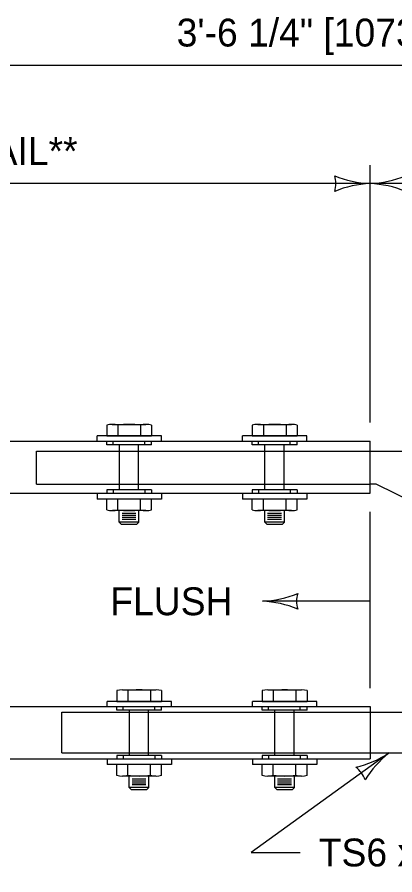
# Model space of a CAD drawing. Extents: x 49991.4 to 50021, y 49987.6 to 50011.4.
# Drawn here: x 50001.527 to 50002.34, y 49993.076 to 49994.923 of the extents above; entities that cross this region are included whole.
import ezdxf

# ---------------------------------------------------------------- set-up
doc = ezdxf.new("R2010")
doc.units = 0
for name, color, linetype in [('Level 1', 7, 'Continuous'), ('Level 2', 7, 'Continuous'), ('Level 3', 7, 'Continuous'), ('Level 4', 7, 'Continuous')]:
    doc.layers.add(name, color=color, linetype=linetype)

msp = doc.modelspace()

# ---------------------------------------------------------------- linework, layer by layer
at = {"layer": 'Level 1'}
for p, q in [((50001.7195, 49994.0446), (50001.7195, 49994.0215)), ((50001.7316, 49994.0461), (50001.8039, 49994.0461)), ((50001.7434, 49994.0446), (50001.7434, 49994.0216)), ((50001.7922, 49994.0446), (50001.7922, 49994.0216)), ((50001.8161, 49994.0446), (50001.8161, 49994.0215)), ((50002.0327, 49994.0446), (50002.0327, 49994.0215)), ((50002.0448, 49994.0461), (50002.1171, 49994.0461)), ((50002.0566, 49994.0446), (50002.0566, 49994.0216)), ((50002.1054, 49994.0446), (50002.1054, 49994.0216)), ((50002.1293, 49994.0446), (50002.1293, 49994.0215)), ((50001.4285, 49994.0102), (50002.2862, 49994.0102)), ((50001.8371, 49994.0215), (50001.6988, 49994.0215)), ((50001.6988, 49994.0102), (50001.6988, 49994.0215)), ((50001.7195, 49994.0215), (50001.8161, 49994.0215)), ((50001.8371, 49994.0102), (50001.8371, 49994.0215)), ((50002.1503, 49994.0215), (50002.012, 49994.0215)), ((50002.012, 49994.0102), (50002.012, 49994.0215)), ((50002.0327, 49994.0215), (50002.1293, 49994.0215)), ((50002.1503, 49994.0102), (50002.1503, 49994.0215)), ((50002.2862, 49993.8979), (50002.2862, 49994.0102)), ((50002.2862, 49993.9889), (50002.717, 49993.9889)), ((50002.2864, 49993.9179), (50002.2997, 49993.9179)), ((50002.717, 49993.7093), (50002.2992, 49993.9177)), ((50001.3976, 49993.8979), (50002.2862, 49993.8979)), ((50001.6988, 49993.8979), (50001.6988, 49993.8853)), ((50001.8371, 49993.8979), (50001.8371, 49993.8853)), ((50002.012, 49993.8979), (50002.012, 49993.8853)), ((50002.1503, 49993.8979), (50002.1503, 49993.8853)), ((50001.8371, 49993.8853), (50001.6988, 49993.8853)), ((50001.8161, 49993.8853), (50001.7195, 49993.8853)), ((50001.7195, 49993.8622), (50001.7195, 49993.8853)), ((50001.7434, 49993.8622), (50001.7434, 49993.8852)), ((50001.7922, 49993.8622), (50001.7922, 49993.8852)), ((50001.8161, 49993.8622), (50001.8161, 49993.8853)), ((50002.1503, 49993.8853), (50002.012, 49993.8853)), ((50002.1293, 49993.8853), (50002.0327, 49993.8853)), ((50002.0327, 49993.8622), (50002.0327, 49993.8853)), ((50002.0566, 49993.8622), (50002.0566, 49993.8852)), ((50002.1054, 49993.8622), (50002.1054, 49993.8852)), ((50002.1293, 49993.8622), (50002.1293, 49993.8853)), ((50001.804, 49993.8607), (50001.7317, 49993.8607)), ((50001.7466, 49993.8358), (50001.7466, 49993.8608)), ((50001.7888, 49993.8358), (50001.7888, 49993.8608)), ((50002.1172, 49993.8607), (50002.0449, 49993.8607)), ((50002.0598, 49993.8358), (50002.0598, 49993.8608)), ((50002.102, 49993.8358), (50002.102, 49993.8608)), ((50001.7527, 49993.8549), (50001.7824, 49993.8549)), ((50001.7527, 49993.8507), (50001.7824, 49993.8507)), ((50001.7527, 49993.8464), (50001.7824, 49993.8464)), ((50001.7527, 49993.8422), (50001.7824, 49993.8422)), ((50002.0659, 49993.8549), (50002.0956, 49993.8549)), ((50002.0659, 49993.8507), (50002.0956, 49993.8507)), ((50002.0659, 49993.8464), (50002.0956, 49993.8464)), ((50002.0659, 49993.8422), (50002.0956, 49993.8422)), ((50001.7888, 49993.8358), (50001.7466, 49993.8358)), ((50001.7466, 49993.8358), (50001.7508, 49993.8316)), ((50001.7508, 49993.8316), (50001.7846, 49993.8316)), ((50001.7888, 49993.8358), (50001.7846, 49993.8316)), ((50002.102, 49993.8358), (50002.0598, 49993.8358)), ((50002.0598, 49993.8358), (50002.064, 49993.8316)), ((50002.064, 49993.8316), (50002.0978, 49993.8316)), ((50002.102, 49993.8358), (50002.0978, 49993.8316)), ((50001.7411, 49993.4731), (50001.7411, 49993.45)), ((50001.7532, 49993.4746), (50001.8255, 49993.4746)), ((50001.765, 49993.4731), (50001.765, 49993.4501)), ((50001.8138, 49993.4731), (50001.8138, 49993.4501)), ((50001.8377, 49993.4731), (50001.8377, 49993.45)), ((50002.0541, 49993.4731), (50002.0541, 49993.45)), ((50002.0662, 49993.4746), (50002.1385, 49993.4746)), ((50002.078, 49993.4731), (50002.078, 49993.4501)), ((50002.1268, 49993.4731), (50002.1268, 49993.4501)), ((50002.1507, 49993.4731), (50002.1507, 49993.45)), ((50000.5502, 49993.4387), (50002.2862, 49993.4387)), ((50001.8587, 49993.45), (50001.7204, 49993.45)), ((50001.7204, 49993.4387), (50001.7204, 49993.45)), ((50001.7411, 49993.45), (50001.8377, 49993.45)), ((50001.8587, 49993.4387), (50001.8587, 49993.45)), ((50002.1717, 49993.45), (50002.0334, 49993.45)), ((50002.0334, 49993.4387), (50002.0334, 49993.45)), ((50002.0541, 49993.45), (50002.1507, 49993.45)), ((50002.1717, 49993.4387), (50002.1717, 49993.45)), ((50002.2862, 49993.4387), (50002.2862, 49993.3264)), ((50002.2862, 49993.4266), (50002.3682, 49993.4266)), ((50000.5502, 49993.3264), (50002.2862, 49993.3264)), ((50001.7204, 49993.3264), (50001.7204, 49993.3138)), ((50001.8587, 49993.3264), (50001.8587, 49993.3138)), ((50002.0334, 49993.3264), (50002.0334, 49993.3138)), ((50002.1717, 49993.3264), (50002.1717, 49993.3138)), ((50002.2862, 49993.3388), (50002.3682, 49993.3388)), ((50001.8587, 49993.3138), (50001.7204, 49993.3138)), ((50001.8377, 49993.3138), (50001.7411, 49993.3138)), ((50001.7411, 49993.2907), (50001.7411, 49993.3138)), ((50001.765, 49993.2907), (50001.765, 49993.3137)), ((50001.8138, 49993.2907), (50001.8138, 49993.3137)), ((50001.8377, 49993.2907), (50001.8377, 49993.3138)), ((50002.1717, 49993.3138), (50002.0334, 49993.3138)), ((50002.1507, 49993.3138), (50002.0541, 49993.3138)), ((50002.0541, 49993.2907), (50002.0541, 49993.3138)), ((50002.078, 49993.2907), (50002.078, 49993.3137)), ((50002.1268, 49993.2907), (50002.1268, 49993.3137)), ((50002.1507, 49993.2907), (50002.1507, 49993.3138)), ((50001.8256, 49993.2892), (50001.7533, 49993.2892)), ((50001.7682, 49993.2643), (50001.7682, 49993.2893)), ((50001.8104, 49993.2643), (50001.8104, 49993.2893)), ((50002.1386, 49993.2892), (50002.0663, 49993.2892)), ((50002.0812, 49993.2643), (50002.0812, 49993.2893)), ((50002.1234, 49993.2643), (50002.1234, 49993.2893)), ((50001.7743, 49993.2834), (50001.804, 49993.2834)), ((50001.7743, 49993.2792), (50001.804, 49993.2792)), ((50001.7743, 49993.2749), (50001.804, 49993.2749)), ((50001.7743, 49993.2707), (50001.804, 49993.2707)), ((50002.0873, 49993.2834), (50002.117, 49993.2834)), ((50002.0873, 49993.2792), (50002.117, 49993.2792)), ((50002.0873, 49993.2749), (50002.117, 49993.2749)), ((50002.0873, 49993.2707), (50002.117, 49993.2707)), ((50001.8104, 49993.2643), (50001.7682, 49993.2643)), ((50001.7682, 49993.2643), (50001.7724, 49993.2601)), ((50001.7724, 49993.2601), (50001.8062, 49993.2601)), ((50001.8104, 49993.2643), (50001.8062, 49993.2601)), ((50002.1234, 49993.2643), (50002.0812, 49993.2643)), ((50002.0812, 49993.2643), (50002.0854, 49993.2601)), ((50002.0854, 49993.2601), (50002.1192, 49993.2601)), ((50002.1234, 49993.2643), (50002.1192, 49993.2601))]:
    msp.add_line(p, q, dxfattribs=at)
for centre, major_axis, start_param, end_param in [((50001.7316, 49994.0344), (0.0242, 0), 1.056847, 2.094396), ((50001.7678, 49993.9994), (0.0966, 0), 1.315951, 1.825641), ((50001.804, 49994.0344), (0.0242, 0), 1.047198, 2.084746), ((50002.0448, 49994.0344), (0.0242, 0), 1.056847, 2.094396), ((50002.081, 49993.9994), (0.0966, 0), 1.315951, 1.825641), ((50002.1172, 49994.0344), (0.0242, 0), 1.047198, 2.084746), ((50001.7316, 49993.8724), (-0.0242, 0), 1.047198, 2.084746), ((50001.7678, 49993.9074), (-0.0966, 0), 1.315951, 1.825641), ((50001.804, 49993.8724), (-0.0242, 0), 1.056847, 2.094396), ((50002.0448, 49993.8724), (-0.0242, 0), 1.047198, 2.084746), ((50002.081, 49993.9074), (-0.0966, 0), 1.315951, 1.825641), ((50002.1172, 49993.8724), (-0.0242, 0), 1.056847, 2.094396), ((50001.7532, 49993.4629), (0.0242, 0), 1.056847, 2.094396), ((50001.7894, 49993.4279), (0.0966, 0), 1.315951, 1.825641), ((50001.8256, 49993.4629), (0.0242, 0), 1.047198, 2.084746), ((50002.0662, 49993.4629), (0.0242, 0), 1.056847, 2.094396), ((50002.1024, 49993.4279), (0.0966, 0), 1.315951, 1.825641), ((50002.1386, 49993.4629), (0.0242, 0), 1.047198, 2.084746), ((50001.7532, 49993.3009), (-0.0242, 0), 1.047198, 2.084746), ((50001.7894, 49993.3359), (-0.0966, 0), 1.315951, 1.825641), ((50001.8256, 49993.3009), (-0.0242, 0), 1.056847, 2.094396), ((50002.0662, 49993.3009), (-0.0242, 0), 1.047198, 2.084746), ((50002.1024, 49993.3359), (-0.0966, 0), 1.315951, 1.825641), ((50002.1386, 49993.3009), (-0.0242, 0), 1.056847, 2.094396)]:
    msp.add_ellipse(centre, major_axis=major_axis, ratio=0.483301, start_param=start_param, end_param=end_param, dxfattribs=at)
at = {"layer": 'Level 3'}
for p, q in [((50001.2319, 49994.8197), (50003.6098, 49994.8197)), ((50002.2862, 49994.0502), (50002.2862, 49994.6046)), ((50002.2862, 49994.5646), (50000.5502, 49994.5646)), ((50003.6098, 49994.5646), (50002.2862, 49994.5646)), ((50002.2862, 49993.4787), (50002.2862, 49993.8579)), ((50002.2862, 49993.6654), (50002.0545, 49993.6654)), ((50002.3273, 49993.3388), (50002.0304, 49993.1246)), ((50002.0304, 49993.1246), (50002.1358, 49993.1246))]:
    msp.add_line(p, q, dxfattribs=at)
for centre, radius, start, end in [((50002.2954, 49994.7867), 0.2223, 247.456, 267.6395), ((50002.158, 49994.5646), 0.0548, 342.1388, 17.8612), ((50002.2747, 49994.7973), 0.233, 272.8273, 292.0772), ((50002.2977, 49994.3319), 0.233, 92.8273, 112.0772), ((50002.277, 49994.3425), 0.2223, 67.456, 87.6395), ((50002.043, 49993.8982), 0.233, 272.8273, 292.0772), ((50002.1827, 49993.6654), 0.0548, 162.1388, 197.8612), ((50002.0454, 49993.4433), 0.2223, 67.456, 87.6395), ((50002.2048, 49993.5243), 0.2223, 283.2637, 303.4472), ((50002.4728, 49993.1568), 0.233, 128.635, 147.8848), ((50002.2234, 49993.2638), 0.0548, 17.9465, 53.6688)]:
    msp.add_arc(centre, radius, start, end, dxfattribs=at)
at = {"layer": 'Level 4'}
for p, q in [((50001.7195, 49994.0023), (50001.7195, 49994.0102)), ((50001.7331, 49994.0023), (50001.7331, 49994.0102)), ((50001.8015, 49994.0023), (50001.8015, 49994.0102)), ((50001.8161, 49994.0023), (50001.8161, 49994.0102)), ((50002.0327, 49994.0023), (50002.0327, 49994.0102)), ((50002.0463, 49994.0023), (50002.0463, 49994.0102)), ((50002.1147, 49994.0023), (50002.1147, 49994.0102)), ((50002.1293, 49994.0023), (50002.1293, 49994.0102)), ((50001.5686, 49993.9177), (50001.5686, 49993.9889)), ((50001.5686, 49993.9889), (50002.2862, 49993.9889)), ((50001.8161, 49994.0023), (50001.7195, 49994.0023)), ((50001.7468, 49993.9051), (50001.7468, 49994.0023)), ((50001.7882, 49993.9051), (50001.7882, 49994.0023)), ((50002.1293, 49994.0023), (50002.0327, 49994.0023)), ((50002.06, 49993.9051), (50002.06, 49994.0023)), ((50002.1014, 49993.9051), (50002.1014, 49994.0023)), ((50001.5686, 49993.9177), (50002.2862, 49993.9177)), ((50001.8161, 49993.9051), (50001.7195, 49993.9051)), ((50001.7195, 49993.9051), (50001.7195, 49993.8979)), ((50001.7331, 49993.9051), (50001.7331, 49993.8979)), ((50001.8015, 49993.9051), (50001.8015, 49993.8979)), ((50001.8161, 49993.9051), (50001.8161, 49993.8979)), ((50002.1293, 49993.9051), (50002.0327, 49993.9051)), ((50002.0327, 49993.9051), (50002.0327, 49993.8979)), ((50002.0463, 49993.9051), (50002.0463, 49993.8979)), ((50002.1147, 49993.9051), (50002.1147, 49993.8979)), ((50002.1293, 49993.9051), (50002.1293, 49993.8979)), ((50001.7411, 49993.4308), (50001.7411, 49993.4387)), ((50001.7547, 49993.4308), (50001.7547, 49993.4387)), ((50001.8231, 49993.4308), (50001.8231, 49993.4387)), ((50001.8377, 49993.4308), (50001.8377, 49993.4387)), ((50002.0541, 49993.4308), (50002.0541, 49993.4387)), ((50002.0677, 49993.4308), (50002.0677, 49993.4387)), ((50002.1361, 49993.4308), (50002.1361, 49993.4387)), ((50002.1507, 49993.4308), (50002.1507, 49993.4387)), ((50001.6229, 49993.3388), (50001.6229, 49993.4266)), ((50001.6229, 49993.4266), (50002.2862, 49993.4266)), ((50001.8377, 49993.4308), (50001.7411, 49993.4308)), ((50001.7684, 49993.3336), (50001.7684, 49993.4308)), ((50001.8098, 49993.3336), (50001.8098, 49993.4308)), ((50002.1507, 49993.4308), (50002.0541, 49993.4308)), ((50002.0814, 49993.3336), (50002.0814, 49993.4308)), ((50002.1228, 49993.3336), (50002.1228, 49993.4308)), ((50001.6229, 49993.3388), (50002.2862, 49993.3388)), ((50001.8377, 49993.3336), (50001.7411, 49993.3336)), ((50001.7411, 49993.3336), (50001.7411, 49993.3264)), ((50001.7547, 49993.3336), (50001.7547, 49993.3264)), ((50001.8231, 49993.3336), (50001.8231, 49993.3264)), ((50001.8377, 49993.3336), (50001.8377, 49993.3264)), ((50002.1507, 49993.3336), (50002.0541, 49993.3336)), ((50002.0541, 49993.3336), (50002.0541, 49993.3264)), ((50002.0677, 49993.3336), (50002.0677, 49993.3264)), ((50002.1361, 49993.3336), (50002.1361, 49993.3264)), ((50002.1507, 49993.3336), (50002.1507, 49993.3264))]:
    msp.add_line(p, q, dxfattribs=at)

# ---------------------------------------------------------------- texts
at = {"layer": 'Level 2'}
for s, p in [('3\'-6 1/4" [1073] (TYP.)**', (50001.8701, 49994.8597)), ('BRIDGE RAIL**', (50001.0861, 49994.6046)), ('FLUSH', (50001.7272, 49993.6354)), ('TS6 x 2 [TS152 x 51] ', (50002.1758, 49993.0946))]:
    msp.add_text(s, height=0.06, dxfattribs=at).set_placement(p)

doc.saveas('drawing.dxf')
